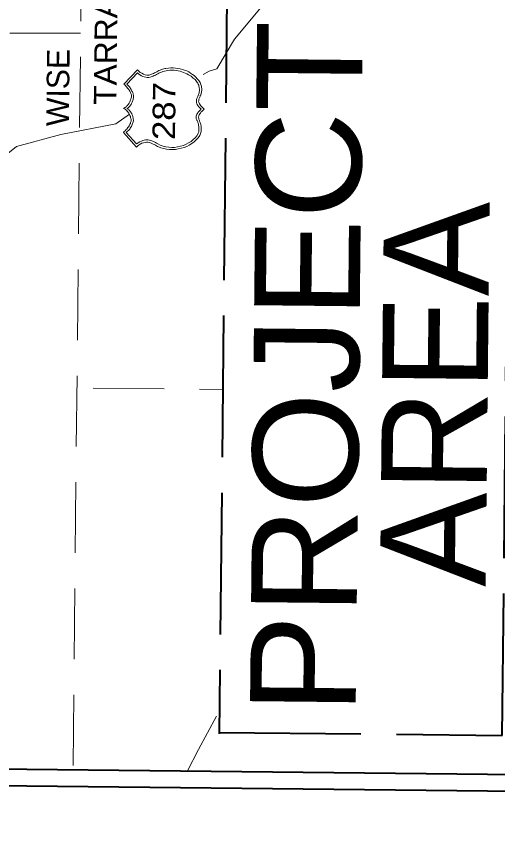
# Model space of a CAD drawing. Extents: x 2356576 to 2377878, y 6966390 to 6990634.
# Drawn here: x 2365706.5 to 2365851.2, y 6968641.2 to 6968885.6 of the extents above; entities that cross this region are included whole.
import ezdxf

# ---------------------------------------------------------------- set-up
doc = ezdxf.new("R2010")
doc.units = 0
doc.header["$LTSCALE"] = 7.1
doc.linetypes.add('LONG_DASHED', pattern=[7.5, 6, -1.5])
doc.linetypes.add('MEDIUM_DASHED', pattern=[4.5, 3, -1.5])
doc.layers.add('19', color=7, linetype='Continuous', lineweight=13)
doc.layers.add('8', color=7, linetype='Continuous', lineweight=13)

msp = doc.modelspace()

# ---------------------------------------------------------------- linework, layer by layer
at = {"layer": '19', "linetype": 'MEDIUM_DASHED'}
for p, q in [((2365729.713, 6969256.812), (2365723.521, 6968659.188)), ((2365725.815, 6968880.556), (2365599.352, 6968880.546)), ((2365729.63, 6968773.855), (2365768.568, 6968773.452))]:
    msp.add_line(p, q, dxfattribs=at)
at = {"layer": '19'}
for p, q in [((2365764.43, 6968869.084), (2365762.647, 6968868.054)), ((2365736.393, 6968853.325), (2365740.503, 6968856.163)), ((2365761.207, 6968665.278), (2365766.711, 6968675.302)), ((2365757.992, 6968658.831), (2365761.207, 6968665.278))]:
    msp.add_line(p, q, dxfattribs=at)
at = {"layer": '19', "lineweight": 40}
msp.add_lwpolyline([(2363758.773, 6990629.355), (2367158.576, 6990592.767), (2366922.891, 6968646.236), (2363523.088, 6968682.826)], close=True, dxfattribs=at)
at = {"layer": '19', "lineweight": 25}
msp.add_lwpolyline([(2365597.072, 6968660.498), (2366217.375, 6968654.072), (2366223.585, 6969253.468), (2365603.282, 6969259.894)], dxfattribs=at)
at = {"layer": '19'}
for points in [[(2365764.43, 6968869.084), (2365766.717, 6968869.78), (2365772.031, 6968878.757), (2365781.232, 6968889.615), (2365789.126, 6968907.142), (2365798.873, 6968921.294), (2365803.859, 6968930.334)], [(2365742.649, 6968846.3), (2365738.674, 6968850.689), (2365738.949, 6968850.927), (2365739.219, 6968851.164), (2365739.434, 6968851.434), (2365739.676, 6968851.639), (2365739.859, 6968851.909), (2365740.041, 6968852.147), (2365740.224, 6968852.385), (2365740.407, 6968852.652), (2365740.557, 6968852.862), (2365740.651, 6968853.129), (2365740.774, 6968853.368), (2365740.837, 6968853.639), (2365740.927, 6968853.878), (2365740.989, 6968854.086), (2365740.993, 6968854.386), (2365740.967, 6968854.658), (2365740.937, 6968854.838), (2365740.851, 6968855.047), (2365740.822, 6968855.287), (2365740.764, 6968855.528), (2365740.647, 6968855.769), (2365740.561, 6968855.982), (2365740.444, 6968856.223), (2365740.326, 6968856.465), (2365740.148, 6968856.675), (2365739.999, 6968856.916), (2365739.793, 6968857.13), (2365739.643, 6968857.34), (2365739.437, 6968857.494), (2365739.226, 6968857.676), (2365738.987, 6968857.767), (2365738.749, 6968857.921), (2365738.991, 6968858.067), (2365739.232, 6968858.216), (2365739.474, 6968858.394), (2365739.656, 6968858.572), (2365739.898, 6968858.777), (2365740.052, 6968859.016), (2365740.235, 6968859.226), (2365740.385, 6968859.464), (2365740.508, 6968859.703), (2365740.662, 6968859.909), (2365740.753, 6968860.208), (2365740.847, 6968860.419), (2365740.91, 6968860.747), (2365741.001, 6968860.958), (2365741.064, 6968861.257), (2365741.066, 6968861.497), (2365741.068, 6968861.705), (2365741.071, 6968861.977), (2365740.985, 6968862.158), (2365740.928, 6968862.427), (2365740.81, 6968862.668), (2365740.72, 6968862.881), (2365740.575, 6968863.09), (2365740.425, 6968863.364), (2365740.28, 6968863.574), (2365740.102, 6968863.815), (2365739.924, 6968864.029), (2365739.715, 6968864.299), (2365739.509, 6968864.514), (2365739.3, 6968864.756), (2365739.062, 6968864.966), (2365738.825, 6968865.209), (2365742.889, 6968869.519), (2365743.277, 6968869.123), (2365743.721, 6968868.73), (2365744.23, 6968868.453), (2365744.736, 6968868.24), (2365745.246, 6968868.022), (2365745.725, 6968867.929), (2365746.113, 6968867.925), (2365746.385, 6968867.922), (2365746.594, 6968867.98), (2365746.867, 6968868.066), (2365747.107, 6968868.155), (2365747.409, 6968868.272), (2365747.71, 6968868.417), (2365748.012, 6968868.566), (2365748.342, 6968868.742), (2365748.703, 6968868.919), (2365749.037, 6968869.095), (2365749.367, 6968869.272), (2365749.761, 6968869.416), (2365750.09, 6968869.564), (2365750.451, 6968869.68), (2365750.785, 6968869.797), (2365751.114, 6968869.882), (2365751.446, 6968869.938), (2365752.227, 6968870.022), (2365752.976, 6968870.102), (2365753.668, 6968870.095), (2365754.387, 6968870), (2365755.078, 6968869.933), (2365755.765, 6968869.805), (2365756.423, 6968869.619), (2365757.081, 6968869.4), (2365757.711, 6968869.185), (2365758.308, 6968868.879)], [(2365759.339, 6968867.276), (2365759.014, 6968867.552), (2365758.624, 6968867.796), (2365758.207, 6968868.04), (2365757.761, 6968868.285), (2365757.284, 6968868.498), (2365756.774, 6968868.715), (2365756.236, 6968868.901), (2365755.697, 6968869.054), (2365755.099, 6968869.212), (2365754.5, 6968869.279), (2365753.9, 6968869.373), (2365753.24, 6968869.38), (2365752.608, 6968869.358), (2365752.008, 6968869.304), (2365751.499, 6968869.25), (2365751.017, 6968869.103), (2365750.564, 6968868.987), (2365750.142, 6968868.812), (2365749.721, 6968868.668), (2365749.359, 6968868.492), (2365748.997, 6968868.283), (2365748.635, 6968868.079), (2365748.305, 6968867.903), (2365747.971, 6968867.754), (2365747.642, 6968867.609), (2365747.308, 6968867.461), (2365746.979, 6968867.376), (2365746.678, 6968867.287), (2365746.318, 6968867.231), (2365745.866, 6968867.208), (2365745.419, 6968867.3), (2365744.968, 6968867.397), (2365744.521, 6968867.522), (2365744.071, 6968867.706), (2365743.653, 6968867.951), (2365743.268, 6968868.255), (2365742.879, 6968868.559), (2365739.664, 6968865.172), (2365739.874, 6968864.958), (2365740.08, 6968864.776), (2365740.318, 6968864.565), (2365740.496, 6968864.351), (2365740.673, 6968864.109), (2365740.851, 6968863.868), (2365741, 6968863.626), (2365741.146, 6968863.385), (2365741.263, 6968863.115), (2365741.412, 6968862.874), (2365741.498, 6968862.601), (2365741.587, 6968862.36), (2365741.645, 6968862.119), (2365741.67, 6968861.911), (2365741.728, 6968861.698), (2365741.726, 6968861.49), (2365741.724, 6968861.278), (2365741.693, 6968861.039), (2365741.659, 6968860.771), (2365741.628, 6968860.559), (2365741.533, 6968860.26), (2365741.443, 6968860.053), (2365741.349, 6968859.814), (2365741.226, 6968859.543), (2365741.104, 6968859.337), (2365740.981, 6968859.066), (2365740.831, 6968858.888), (2365740.677, 6968858.681), (2365740.495, 6968858.443), (2365740.285, 6968858.265), (2365740.103, 6968858.087), (2365739.829, 6968857.91), (2365740.067, 6968857.727), (2365740.277, 6968857.545), (2365740.455, 6968857.363), (2365740.601, 6968857.182), (2365740.719, 6968856.969), (2365740.87, 6968856.819), (2365741.015, 6968856.578), (2365741.165, 6968856.396), (2365741.223, 6968856.183), (2365741.341, 6968855.942), (2365741.399, 6968855.761), (2365741.484, 6968855.521), (2365741.514, 6968855.312), (2365741.6, 6968855.099), (2365741.629, 6968854.859), (2365741.655, 6968854.651), (2365741.685, 6968854.438), (2365741.682, 6968854.138), (2365741.619, 6968853.871), (2365741.556, 6968853.572), (2365741.462, 6968853.333), (2365741.339, 6968853.034), (2365741.215, 6968852.735), (2365741.065, 6968852.525), (2365740.91, 6968852.226), (2365740.759, 6968851.96), (2365740.577, 6968851.722), (2365740.363, 6968851.512), (2365740.18, 6968851.246), (2365739.938, 6968851.036)], [(2365739.546, 6968850.68), (2365742.658, 6968847.228), (2365743.142, 6968847.583), (2365743.657, 6968847.878), (2365744.107, 6968848.085), (2365744.53, 6968848.289), (2365744.95, 6968848.376), (2365745.371, 6968848.46), (2365745.732, 6968848.488), (2365746.123, 6968848.452), (2365746.51, 6968848.36), (2365746.87, 6968848.296), (2365747.26, 6968848.172), (2365747.619, 6968847.989), (2365747.945, 6968847.833), (2365748.303, 6968847.65), (2365748.633, 6968847.438), (2365748.991, 6968847.222), (2365749.767, 6968846.826), (2365750.632, 6968846.545), (2365751.41, 6968846.329), (2365752.309, 6968846.228), (2365753.208, 6968846.191), (2365754.081, 6968846.21), (2365754.982, 6968846.352), (2365755.824, 6968846.524), (2365756.699, 6968846.783), (2365757.51, 6968847.134), (2365758.295, 6968847.546), (2365759.019, 6968847.991), (2365759.625, 6968848.524), (2365760.231, 6968849.086), (2365760.749, 6968849.713), (2365761.176, 6968850.336), (2365761.205, 6968850.488), (2365761.299, 6968850.667), (2365761.329, 6968850.875), (2365761.332, 6968851.115), (2365761.366, 6968851.294), (2365761.396, 6968851.534), (2365761.399, 6968851.774), (2365761.373, 6968852.014), (2365761.344, 6968852.287), (2365761.346, 6968852.495), (2365761.289, 6968852.767), (2365761.263, 6968853.008), (2365761.233, 6968853.216), (2365761.148, 6968853.457), (2365761.09, 6968853.669), (2365761.032, 6968853.85), (2365760.914, 6968854.031), (2365760.824, 6968854.24), (2365760.738, 6968854.393), (2365760.648, 6968854.602), (2365760.59, 6968854.815), (2365760.564, 6968854.995), (2365760.534, 6968855.203), (2365760.536, 6968855.415), (2365760.57, 6968855.623), (2365760.633, 6968855.894), (2365760.724, 6968856.133), (2365760.906, 6968856.371), (2365761.061, 6968856.67), (2365761.364, 6968856.967), (2365761.668, 6968857.324), (2365762.059, 6968857.648), (2365761.644, 6968858.044), (2365761.347, 6968858.407), (2365761.083, 6968858.738), (2365760.874, 6968859.072), (2365760.757, 6968859.341), (2365760.672, 6968859.614), (2365760.614, 6968859.855), (2365760.617, 6968860.155), (2365760.647, 6968860.362), (2365760.682, 6968860.574), (2365760.772, 6968860.841), (2365760.867, 6968861.08), (2365760.957, 6968861.291), (2365761.08, 6968861.53), (2365761.174, 6968861.797), (2365761.297, 6968862.068), (2365761.36, 6968862.335), (2365761.451, 6968862.606), (2365761.486, 6968862.874), (2365761.517, 6968863.173), (2365761.551, 6968863.445), (2365761.523, 6968863.745), (2365761.497, 6968864.014), (2365761.468, 6968864.314), (2365761.384, 6968864.615), (2365761.326, 6968864.888), (2365761.15, 6968865.189), (2365761.032, 6968865.459), (2365760.855, 6968865.732), (2365760.678, 6968866.034), (2365760.441, 6968866.277), (2365760.204, 6968866.547), (2365759.966, 6968866.79), (2365759.637, 6968867.033), (2365759.339, 6968867.276)], [(2365758.308, 6968868.879), (2365758.872, 6968868.541), (2365759.408, 6968868.148), (2365759.944, 6968867.782), (2365760.419, 6968867.265), (2365760.894, 6968866.812), (2365761.341, 6968866.267), (2365761.546, 6968865.965), (2365761.723, 6968865.691), (2365761.84, 6968865.39), (2365761.957, 6968865.089), (2365762.074, 6968864.82), (2365762.131, 6968864.519), (2365762.187, 6968864.187), (2365762.216, 6968863.918), (2365762.241, 6968863.586), (2365762.21, 6968863.286), (2365762.175, 6968863.019), (2365762.145, 6968862.779), (2365762.049, 6968862.48), (2365762.019, 6968862.24), (2365761.925, 6968862.001), (2365761.802, 6968861.762), (2365761.74, 6968861.523), (2365761.649, 6968861.284), (2365761.527, 6968861.105), (2365761.433, 6968860.866), (2365761.403, 6968860.687), (2365761.34, 6968860.447), (2365761.306, 6968860.208), (2365761.304, 6968859.996), (2365761.361, 6968859.755), (2365761.45, 6968859.486), (2365761.596, 6968859.244), (2365761.745, 6968858.971), (2365761.982, 6968858.668), (2365762.219, 6968858.366), (2365762.575, 6968858.034), (2365762.96, 6968857.67), (2365762.596, 6968857.314), (2365762.293, 6968857.017), (2365761.99, 6968856.748), (2365761.807, 6968856.45), (2365761.625, 6968856.244), (2365761.474, 6968856.006), (2365761.38, 6968855.795), (2365761.318, 6968855.587), (2365761.288, 6968855.407), (2365761.286, 6968855.195), (2365761.312, 6968855.015), (2365761.37, 6968854.807), (2365761.4, 6968854.654), (2365761.458, 6968854.446), (2365761.544, 6968854.233), (2365761.602, 6968854.052), (2365761.692, 6968853.871), (2365761.75, 6968853.663), (2365761.836, 6968853.422), (2365761.925, 6968853.149), (2365761.95, 6968852.908), (2365762.008, 6968852.64), (2365762.065, 6968852.367), (2365762.094, 6968852.127), (2365762.091, 6968851.827), (2365762.088, 6968851.559), (2365762.086, 6968851.287), (2365762.05, 6968850.959), (2365761.959, 6968850.688), (2365761.896, 6968850.389), (2365761.773, 6968850.09), (2365761.618, 6968849.792), (2365761.163, 6968849.108), (2365760.584, 6968848.454), (2365759.95, 6968847.829), (2365759.252, 6968847.328), (2365758.499, 6968846.856), (2365757.743, 6968846.472), (2365756.9, 6968846.18), (2365756.03, 6968845.921), (2365755.155, 6968845.718), (2365754.314, 6968845.607), (2365753.414, 6968845.556), (2365752.542, 6968845.566), (2365751.643, 6968845.667), (2365750.836, 6968845.823), (2365749.967, 6968846.072), (2365749.222, 6968846.38), (2365748.923, 6968846.503), (2365748.625, 6968846.658), (2365748.295, 6968846.842), (2365747.969, 6968847.025), (2365747.611, 6968847.209), (2365747.252, 6968847.392), (2365746.862, 6968847.544), (2365746.475, 6968847.64), (2365746.056, 6968847.733), (2365745.604, 6968847.738), (2365745.184, 6968847.714), (2365744.702, 6968847.599), (2365744.221, 6968847.424), (2365743.678, 6968847.157)], [(2365598.457, 6968794.115), (2365606.633, 6968801.443), (2365622.603, 6968810.818), (2365640.203, 6968818.468), (2365659.761, 6968821.265), (2365670.842, 6968822.051), (2365684.124, 6968826.801), (2365695.605, 6968837.723), (2365706.497, 6968846.495), (2365719.827, 6968850.105), (2365736.393, 6968853.325)], [(2365739.938, 6968851.036), (2365739.728, 6968850.859), (2365739.546, 6968850.68)], [(2365743.678, 6968847.157), (2365743.166, 6968846.803), (2365742.649, 6968846.3)]]:
    msp.add_lwpolyline(points, dxfattribs=at)
at = {"layer": '19', "linetype": 'LONG_DASHED', "lineweight": 40}
msp.add_lwpolyline([(2365767.5, 6968670.405), (2365852.579, 6968669.524), (2365854.981, 6968901.299), (2365769.901, 6968902.181), (2365767.496, 6968669.985)], dxfattribs=at)
at = {"layer": '8', "linetype": 'MEDIUM_DASHED'}
for p, q in [((2365729.713, 6969256.812), (2365723.521, 6968659.188)), ((2365725.815, 6968880.556), (2365599.352, 6968880.546)), ((2365729.63, 6968773.855), (2365768.568, 6968773.452))]:
    msp.add_line(p, q, dxfattribs=at)
at = {"layer": '8'}
for p, q in [((2365764.43, 6968869.084), (2365762.647, 6968868.054)), ((2365736.393, 6968853.325), (2365740.503, 6968856.163)), ((2365761.207, 6968665.278), (2365766.711, 6968675.302)), ((2365757.992, 6968658.831), (2365761.207, 6968665.278))]:
    msp.add_line(p, q, dxfattribs=at)
at = {"layer": '8', "lineweight": 40}
for points in [[(2363753.827, 6990634.409), (2367163.63, 6990597.713), (2366927.837, 6968641.182), (2363518.034, 6968677.88)], [(2363758.773, 6990629.355), (2367158.576, 6990592.767), (2366922.891, 6968646.236), (2363523.088, 6968682.826)]]:
    msp.add_lwpolyline(points, close=True, dxfattribs=at)
at = {"layer": '8', "lineweight": 25}
msp.add_lwpolyline([(2365597.072, 6968660.498), (2366217.375, 6968654.072), (2366223.585, 6969253.468), (2365603.282, 6969259.894)], dxfattribs=at)
at = {"layer": '8'}
for points in [[(2365764.43, 6968869.084), (2365766.717, 6968869.78), (2365772.031, 6968878.757), (2365781.232, 6968889.615), (2365789.126, 6968907.142), (2365798.873, 6968921.294), (2365803.859, 6968930.334)], [(2365742.649, 6968846.3), (2365738.674, 6968850.689), (2365738.949, 6968850.927), (2365739.219, 6968851.164), (2365739.434, 6968851.434), (2365739.676, 6968851.639), (2365739.859, 6968851.909), (2365740.041, 6968852.147), (2365740.224, 6968852.385), (2365740.407, 6968852.652), (2365740.557, 6968852.862), (2365740.651, 6968853.129), (2365740.774, 6968853.368), (2365740.837, 6968853.639), (2365740.927, 6968853.878), (2365740.989, 6968854.086), (2365740.993, 6968854.386), (2365740.967, 6968854.658), (2365740.937, 6968854.838), (2365740.851, 6968855.047), (2365740.822, 6968855.287), (2365740.764, 6968855.528), (2365740.647, 6968855.769), (2365740.561, 6968855.982), (2365740.444, 6968856.223), (2365740.326, 6968856.465), (2365740.148, 6968856.675), (2365739.999, 6968856.916), (2365739.793, 6968857.13), (2365739.643, 6968857.34), (2365739.437, 6968857.494), (2365739.226, 6968857.676), (2365738.987, 6968857.767), (2365738.749, 6968857.921), (2365738.991, 6968858.067), (2365739.232, 6968858.216), (2365739.474, 6968858.394), (2365739.656, 6968858.572), (2365739.898, 6968858.777), (2365740.052, 6968859.016), (2365740.235, 6968859.226), (2365740.385, 6968859.464), (2365740.508, 6968859.703), (2365740.662, 6968859.909), (2365740.753, 6968860.208), (2365740.847, 6968860.419), (2365740.91, 6968860.747), (2365741.001, 6968860.958), (2365741.064, 6968861.257), (2365741.066, 6968861.497), (2365741.068, 6968861.705), (2365741.071, 6968861.977), (2365740.985, 6968862.158), (2365740.928, 6968862.427), (2365740.81, 6968862.668), (2365740.72, 6968862.881), (2365740.575, 6968863.09), (2365740.425, 6968863.364), (2365740.28, 6968863.574), (2365740.102, 6968863.815), (2365739.924, 6968864.029), (2365739.715, 6968864.299), (2365739.509, 6968864.514), (2365739.3, 6968864.756), (2365739.062, 6968864.966), (2365738.825, 6968865.209), (2365742.889, 6968869.519), (2365743.277, 6968869.123), (2365743.721, 6968868.73), (2365744.23, 6968868.453), (2365744.736, 6968868.24), (2365745.246, 6968868.022), (2365745.725, 6968867.929), (2365746.113, 6968867.925), (2365746.385, 6968867.922), (2365746.594, 6968867.98), (2365746.867, 6968868.066), (2365747.107, 6968868.155), (2365747.409, 6968868.272), (2365747.71, 6968868.417), (2365748.012, 6968868.566), (2365748.342, 6968868.742), (2365748.703, 6968868.919), (2365749.037, 6968869.095), (2365749.367, 6968869.272), (2365749.761, 6968869.416), (2365750.09, 6968869.564), (2365750.451, 6968869.68), (2365750.785, 6968869.797), (2365751.114, 6968869.882), (2365751.446, 6968869.938), (2365752.227, 6968870.022), (2365752.976, 6968870.102), (2365753.668, 6968870.095), (2365754.387, 6968870), (2365755.078, 6968869.933), (2365755.765, 6968869.805), (2365756.423, 6968869.619), (2365757.081, 6968869.4), (2365757.711, 6968869.185), (2365758.308, 6968868.879)], [(2365759.339, 6968867.276), (2365759.014, 6968867.552), (2365758.624, 6968867.796), (2365758.207, 6968868.04), (2365757.761, 6968868.285), (2365757.284, 6968868.498), (2365756.774, 6968868.715), (2365756.236, 6968868.901), (2365755.697, 6968869.054), (2365755.099, 6968869.212), (2365754.5, 6968869.279), (2365753.9, 6968869.373), (2365753.24, 6968869.38), (2365752.608, 6968869.358), (2365752.008, 6968869.304), (2365751.499, 6968869.25), (2365751.017, 6968869.103), (2365750.564, 6968868.987), (2365750.142, 6968868.812), (2365749.721, 6968868.668), (2365749.359, 6968868.492), (2365748.997, 6968868.283), (2365748.635, 6968868.079), (2365748.305, 6968867.903), (2365747.971, 6968867.754), (2365747.642, 6968867.609), (2365747.308, 6968867.461), (2365746.979, 6968867.376), (2365746.678, 6968867.287), (2365746.318, 6968867.231), (2365745.866, 6968867.208), (2365745.419, 6968867.3), (2365744.968, 6968867.397), (2365744.521, 6968867.522), (2365744.071, 6968867.706), (2365743.653, 6968867.951), (2365743.268, 6968868.255), (2365742.879, 6968868.559), (2365739.664, 6968865.172), (2365739.874, 6968864.958), (2365740.08, 6968864.776), (2365740.318, 6968864.565), (2365740.496, 6968864.351), (2365740.673, 6968864.109), (2365740.851, 6968863.868), (2365741, 6968863.626), (2365741.146, 6968863.385), (2365741.263, 6968863.115), (2365741.412, 6968862.874), (2365741.498, 6968862.601), (2365741.587, 6968862.36), (2365741.645, 6968862.119), (2365741.67, 6968861.911), (2365741.728, 6968861.698), (2365741.726, 6968861.49), (2365741.724, 6968861.278), (2365741.693, 6968861.039), (2365741.659, 6968860.771), (2365741.628, 6968860.559), (2365741.533, 6968860.26), (2365741.443, 6968860.053), (2365741.349, 6968859.814), (2365741.226, 6968859.543), (2365741.104, 6968859.337), (2365740.981, 6968859.066), (2365740.831, 6968858.888), (2365740.677, 6968858.681), (2365740.495, 6968858.443), (2365740.285, 6968858.265), (2365740.103, 6968858.087), (2365739.829, 6968857.91), (2365740.067, 6968857.727), (2365740.277, 6968857.545), (2365740.455, 6968857.363), (2365740.601, 6968857.182), (2365740.719, 6968856.969), (2365740.87, 6968856.819), (2365741.015, 6968856.578), (2365741.165, 6968856.396), (2365741.223, 6968856.183), (2365741.341, 6968855.942), (2365741.399, 6968855.761), (2365741.484, 6968855.521), (2365741.514, 6968855.312), (2365741.6, 6968855.099), (2365741.629, 6968854.859), (2365741.655, 6968854.651), (2365741.685, 6968854.438), (2365741.682, 6968854.138), (2365741.619, 6968853.871), (2365741.556, 6968853.572), (2365741.462, 6968853.333), (2365741.339, 6968853.034), (2365741.215, 6968852.735), (2365741.065, 6968852.525), (2365740.91, 6968852.226), (2365740.759, 6968851.96), (2365740.577, 6968851.722), (2365740.363, 6968851.512), (2365740.18, 6968851.246), (2365739.938, 6968851.036)], [(2365739.546, 6968850.68), (2365742.658, 6968847.228), (2365743.142, 6968847.583), (2365743.657, 6968847.878), (2365744.107, 6968848.085), (2365744.53, 6968848.289), (2365744.95, 6968848.376), (2365745.371, 6968848.46), (2365745.732, 6968848.488), (2365746.123, 6968848.452), (2365746.51, 6968848.36), (2365746.87, 6968848.296), (2365747.26, 6968848.172), (2365747.619, 6968847.989), (2365747.945, 6968847.833), (2365748.303, 6968847.65), (2365748.633, 6968847.438), (2365748.991, 6968847.222), (2365749.767, 6968846.826), (2365750.632, 6968846.545), (2365751.41, 6968846.329), (2365752.309, 6968846.228), (2365753.208, 6968846.191), (2365754.081, 6968846.21), (2365754.982, 6968846.352), (2365755.824, 6968846.524), (2365756.699, 6968846.783), (2365757.51, 6968847.134), (2365758.295, 6968847.546), (2365759.019, 6968847.991), (2365759.625, 6968848.524), (2365760.231, 6968849.086), (2365760.749, 6968849.713), (2365761.176, 6968850.336), (2365761.205, 6968850.488), (2365761.299, 6968850.667), (2365761.329, 6968850.875), (2365761.332, 6968851.115), (2365761.366, 6968851.294), (2365761.396, 6968851.534), (2365761.399, 6968851.774), (2365761.373, 6968852.014), (2365761.344, 6968852.287), (2365761.346, 6968852.495), (2365761.289, 6968852.767), (2365761.263, 6968853.008), (2365761.233, 6968853.216), (2365761.148, 6968853.457), (2365761.09, 6968853.669), (2365761.032, 6968853.85), (2365760.914, 6968854.031), (2365760.824, 6968854.24), (2365760.738, 6968854.393), (2365760.648, 6968854.602), (2365760.59, 6968854.815), (2365760.564, 6968854.995), (2365760.534, 6968855.203), (2365760.536, 6968855.415), (2365760.57, 6968855.623), (2365760.633, 6968855.894), (2365760.724, 6968856.133), (2365760.906, 6968856.371), (2365761.061, 6968856.67), (2365761.364, 6968856.967), (2365761.668, 6968857.324), (2365762.059, 6968857.648), (2365761.644, 6968858.044), (2365761.347, 6968858.407), (2365761.083, 6968858.738), (2365760.874, 6968859.072), (2365760.757, 6968859.341), (2365760.672, 6968859.614), (2365760.614, 6968859.855), (2365760.617, 6968860.155), (2365760.647, 6968860.362), (2365760.682, 6968860.574), (2365760.772, 6968860.841), (2365760.867, 6968861.08), (2365760.957, 6968861.291), (2365761.08, 6968861.53), (2365761.174, 6968861.797), (2365761.297, 6968862.068), (2365761.36, 6968862.335), (2365761.451, 6968862.606), (2365761.486, 6968862.874), (2365761.517, 6968863.173), (2365761.551, 6968863.445), (2365761.523, 6968863.745), (2365761.497, 6968864.014), (2365761.468, 6968864.314), (2365761.384, 6968864.615), (2365761.326, 6968864.888), (2365761.15, 6968865.189), (2365761.032, 6968865.459), (2365760.855, 6968865.732), (2365760.678, 6968866.034), (2365760.441, 6968866.277), (2365760.204, 6968866.547), (2365759.966, 6968866.79), (2365759.637, 6968867.033), (2365759.339, 6968867.276)], [(2365758.308, 6968868.879), (2365758.872, 6968868.541), (2365759.408, 6968868.148), (2365759.944, 6968867.782), (2365760.419, 6968867.265), (2365760.894, 6968866.812), (2365761.341, 6968866.267), (2365761.546, 6968865.965), (2365761.723, 6968865.691), (2365761.84, 6968865.39), (2365761.957, 6968865.089), (2365762.074, 6968864.82), (2365762.131, 6968864.519), (2365762.187, 6968864.187), (2365762.216, 6968863.918), (2365762.241, 6968863.586), (2365762.21, 6968863.286), (2365762.175, 6968863.019), (2365762.145, 6968862.779), (2365762.049, 6968862.48), (2365762.019, 6968862.24), (2365761.925, 6968862.001), (2365761.802, 6968861.762), (2365761.74, 6968861.523), (2365761.649, 6968861.284), (2365761.527, 6968861.105), (2365761.433, 6968860.866), (2365761.403, 6968860.687), (2365761.34, 6968860.447), (2365761.306, 6968860.208), (2365761.304, 6968859.996), (2365761.361, 6968859.755), (2365761.45, 6968859.486), (2365761.596, 6968859.244), (2365761.745, 6968858.971), (2365761.982, 6968858.668), (2365762.219, 6968858.366), (2365762.575, 6968858.034), (2365762.96, 6968857.67), (2365762.596, 6968857.314), (2365762.293, 6968857.017), (2365761.99, 6968856.748), (2365761.807, 6968856.45), (2365761.625, 6968856.244), (2365761.474, 6968856.006), (2365761.38, 6968855.795), (2365761.318, 6968855.587), (2365761.288, 6968855.407), (2365761.286, 6968855.195), (2365761.312, 6968855.015), (2365761.37, 6968854.807), (2365761.4, 6968854.654), (2365761.458, 6968854.446), (2365761.544, 6968854.233), (2365761.602, 6968854.052), (2365761.692, 6968853.871), (2365761.75, 6968853.663), (2365761.836, 6968853.422), (2365761.925, 6968853.149), (2365761.95, 6968852.908), (2365762.008, 6968852.64), (2365762.065, 6968852.367), (2365762.094, 6968852.127), (2365762.091, 6968851.827), (2365762.088, 6968851.559), (2365762.086, 6968851.287), (2365762.05, 6968850.959), (2365761.959, 6968850.688), (2365761.896, 6968850.389), (2365761.773, 6968850.09), (2365761.618, 6968849.792), (2365761.163, 6968849.108), (2365760.584, 6968848.454), (2365759.95, 6968847.829), (2365759.252, 6968847.328), (2365758.499, 6968846.856), (2365757.743, 6968846.472), (2365756.9, 6968846.18), (2365756.03, 6968845.921), (2365755.155, 6968845.718), (2365754.314, 6968845.607), (2365753.414, 6968845.556), (2365752.542, 6968845.566), (2365751.643, 6968845.667), (2365750.836, 6968845.823), (2365749.967, 6968846.072), (2365749.222, 6968846.38), (2365748.923, 6968846.503), (2365748.625, 6968846.658), (2365748.295, 6968846.842), (2365747.969, 6968847.025), (2365747.611, 6968847.209), (2365747.252, 6968847.392), (2365746.862, 6968847.544), (2365746.475, 6968847.64), (2365746.056, 6968847.733), (2365745.604, 6968847.738), (2365745.184, 6968847.714), (2365744.702, 6968847.599), (2365744.221, 6968847.424), (2365743.678, 6968847.157)], [(2365598.457, 6968794.115), (2365606.633, 6968801.443), (2365622.603, 6968810.818), (2365640.203, 6968818.468), (2365659.761, 6968821.265), (2365670.842, 6968822.051), (2365684.124, 6968826.801), (2365695.605, 6968837.723), (2365706.497, 6968846.495), (2365719.827, 6968850.105), (2365736.393, 6968853.325)], [(2365739.938, 6968851.036), (2365739.728, 6968850.859), (2365739.546, 6968850.68)], [(2365743.678, 6968847.157), (2365743.166, 6968846.803), (2365742.649, 6968846.3)]]:
    msp.add_lwpolyline(points, dxfattribs=at)
at = {"layer": '8', "linetype": 'LONG_DASHED', "lineweight": 40}
msp.add_lwpolyline([(2365767.5, 6968670.405), (2365852.579, 6968669.524), (2365854.981, 6968901.299), (2365769.901, 6968902.181), (2365767.496, 6968669.985)], dxfattribs=at)

# ---------------------------------------------------------------- texts
at = {"layer": '19'}
for s, height, width, p in [('TARRANT', 6.798, 1.05, (2365736.572, 6968858.964)), ('PROJECT', 31.77, 1.05, (2365808.482, 6968675.829)), ('287', 6.798, 1.15, (2365754.191, 6968848.369))]:
    msp.add_text(s, height=height, rotation=89.406, dxfattribs=dict(at, width=width)).set_placement(p)
for s, height, p in [('WISE', 6.798, (2365722.284, 6968852.539)), ('AREA', 31.77, (2365847.581, 6968714.13))]:
    msp.add_text(s, height=height, rotation=89.406, dxfattribs=at).set_placement(p)
at = {"layer": '8'}
for s, height, width, p in [('TARRANT', 6.798, 1.05, (2365736.572, 6968858.964)), ('PROJECT', 31.77, 1.05, (2365808.482, 6968675.829)), ('287', 6.798, 1.15, (2365754.191, 6968848.369))]:
    msp.add_text(s, height=height, rotation=89.406, dxfattribs=dict(at, width=width)).set_placement(p)
for s, height, p in [('WISE', 6.798, (2365722.284, 6968852.539)), ('AREA', 31.77, (2365847.581, 6968714.13))]:
    msp.add_text(s, height=height, rotation=89.406, dxfattribs=at).set_placement(p)

doc.saveas('drawing.dxf')
